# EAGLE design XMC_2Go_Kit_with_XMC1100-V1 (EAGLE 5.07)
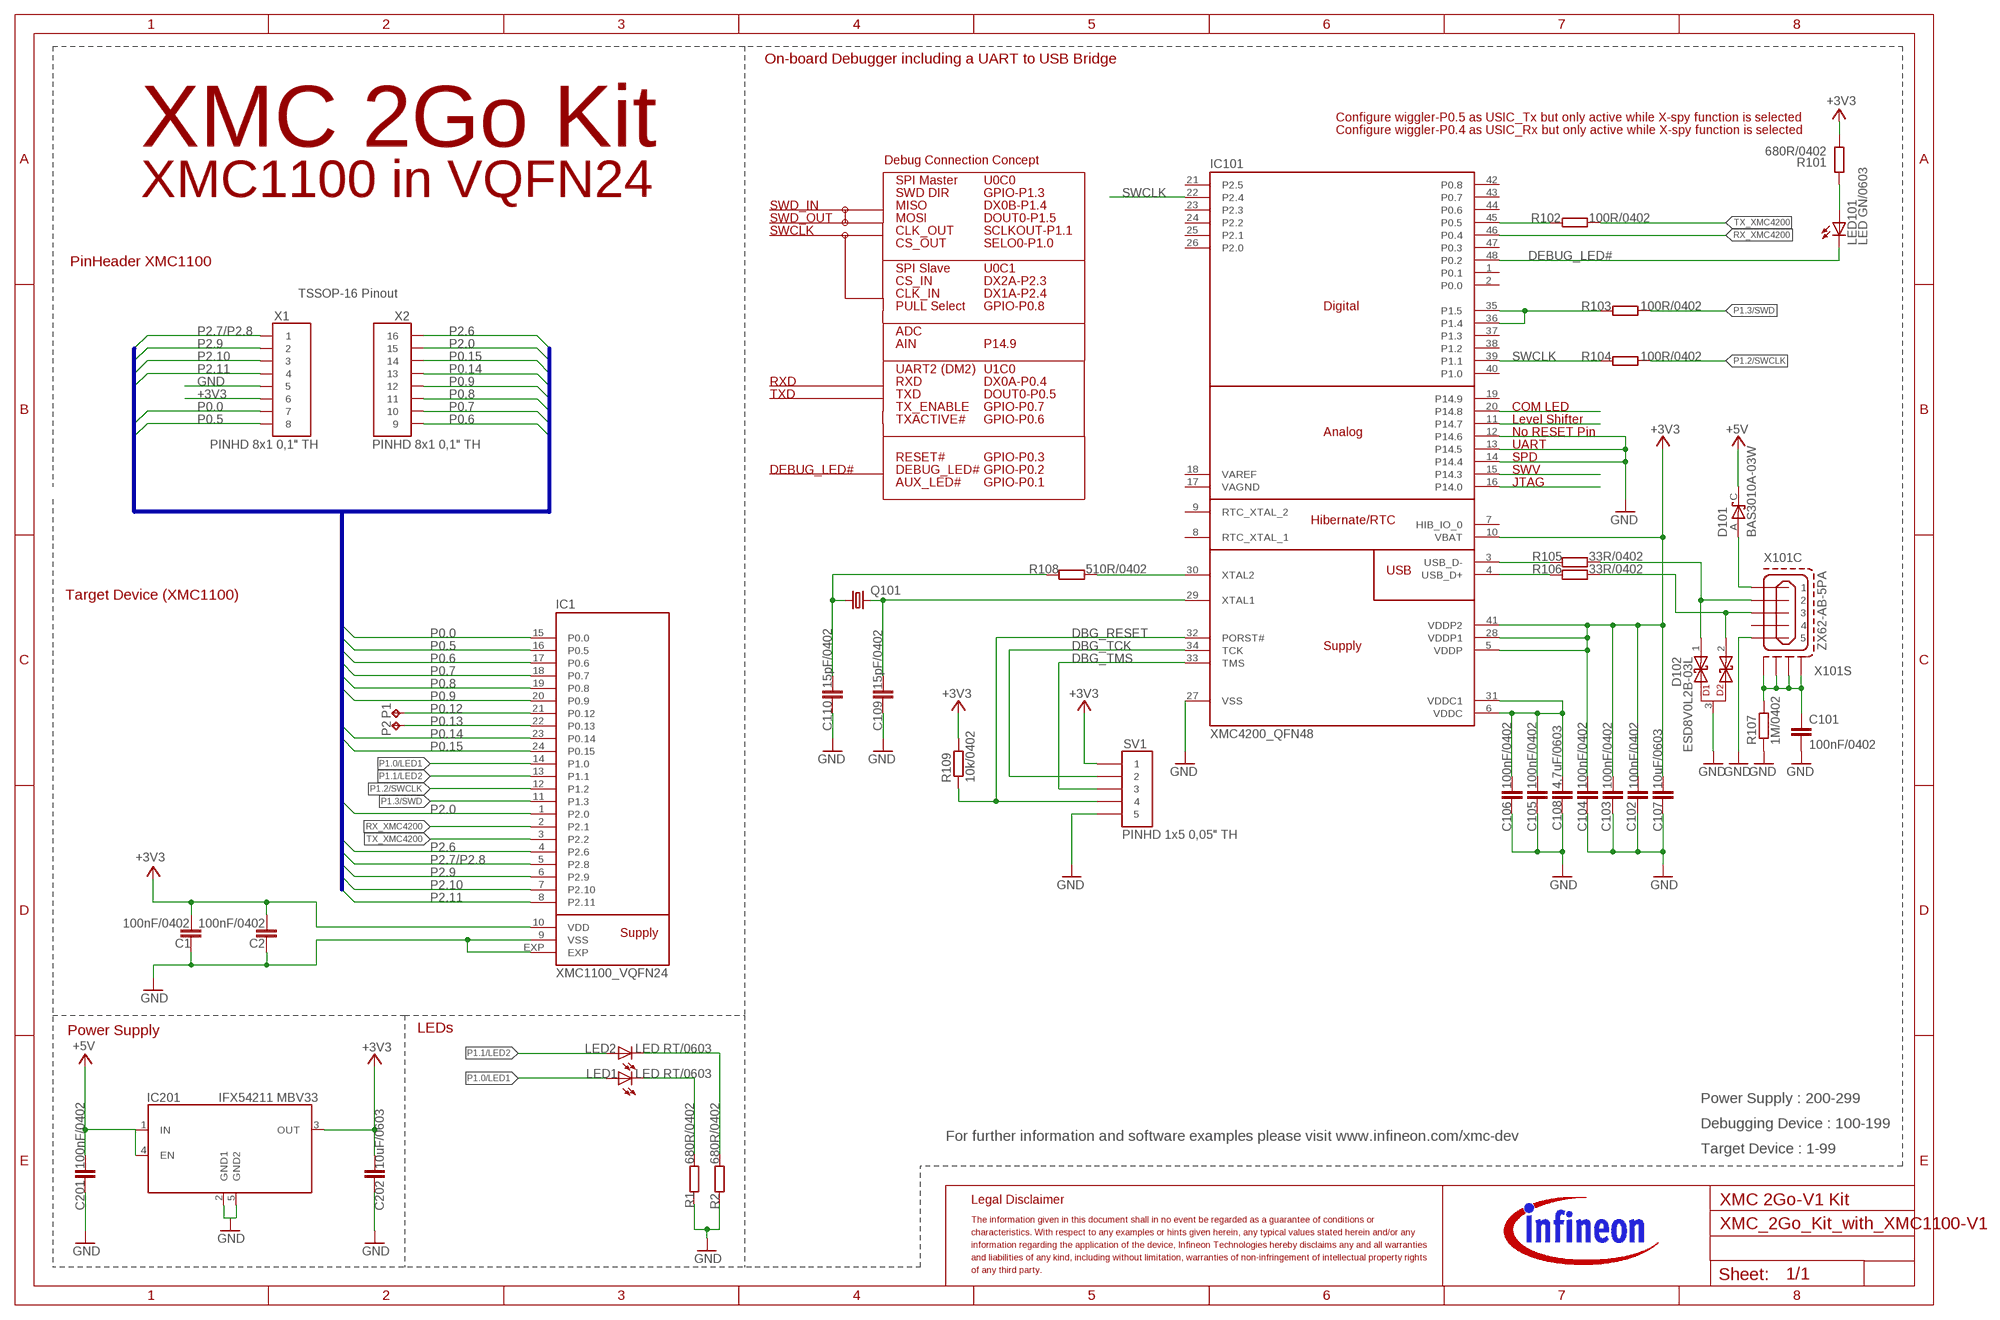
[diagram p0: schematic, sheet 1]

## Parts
C1  100nF/0402  C-EUC0402  [C0402]
C2  100nF/0402  C-EUC0402  [C0402]
C101  100nF/0402  C-EUC0402  [C0402]
C102  100nF/0402  C-EUC0402  [C0402]
C103  100nF/0402  C-EUC0402  [C0402]
C104  100nF/0402  C-EUC0402  [C0402]
C105  100nF/0402  C-EUC0402  [C0402]
C106  100nF/0402  C-EUC0402  [C0402]
C107  10uF/0603  C-EUC0603  [C0603]
C108  4,7uF/0603  C-EUC0603  [C0603]
C109  15pF/0402  C-EUC0402  [C0402]
C110  15pF/0402  C-EUC0402  [C0402]
C201  100nF/0402  C-EUC0402  [C0402]
C202  10uF/0603  C-EUC0603  [C0603]
D101  BAS3010A-03W  BAT60  [SOD323-R]
D102  ESD8V0L2B-03L  [TSLP-3-1]
IC1  XMC1100_VQFN24  [VQFN24]
IC101  XMC4200_QFN48  [QFN-48-7X7]
IC201  IFX54211 MBV33  TLS202B1MBV  [SCT595_INFINEON]
LED1  LED RT/0603  LEDCHIPLED_0603  [CHIPLED_0603]
LED2  LED RT/0603  LEDCHIPLED_0603  [CHIPLED_0603]
LED101  LED GN/0603  LEDCHIPLED_0603  [CHIPLED_0603]
P1  TPTP07R  [TP07R]
P2  TPTP07R  [TP07R]
Q101  NX3225_2  [32X25_4PAD]
R1  680R/0402  R-EU_R0402  [R0402]
R2  680R/0402  R-EU_R0402  [R0402]
R101  680R/0402  R-EU_R0402  [R0402]
R102  100R/0402  R-EU_R0402  [R0402]
R103  100R/0402  R-EU_R0402  [R0402]
R104  100R/0402  R-EU_R0402  [R0402]
R105  33R/0402  R-EU_R0402  [R0402]
R106  33R/0402  R-EU_R0402  [R0402]
R107  1M/0402  R-EU_R06030402  [R0402]
R108  510R/0402  R-EU_R0402  [R0402]
R109  10k/0402  R-EU_R0402  [R0402]
SV1  PINHD 1x5 0,05" TH  PINHEAD_127  [PINHEAD_127]
X1  PINHD 8x1 0,1" TH  PINHD_1X8_SP  [PINHD_1X8_SP]
X2  PINHD 8x1 0,1" TH  PINHD_1X8_SP  [PINHD_1X8_SP]
X101  ZX62-AB-5PA  ZX62-AB-5PA_MICRO-USB  [ZX62-AB-5PA_MICRO-USB]

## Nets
+3V3: C1.2 C2.2 C102.1 C103.1 C104.1 C107.1 C202.1 IC1.10(VDD) IC101.5(VDDP) IC101.10(VBAT) IC101.28(VDDP1) IC101.41(VDDP2) IC201.3(OUT) R101.1 R109.2 SV1.P$1 X1.6
+5V: C201.1 D101.C IC201.1(IN) IC201.4(EN)
DBG_RESET: IC101.32(PORST#) R109.1 SV1.P$4
DBG_TCK: IC101.34(TCK) SV1.P$2
DBG_TMS: IC101.33(TMS) SV1.P$3
DEBUG_LED#: IC101.48(P0.2) LED101.C
GND: C1.1 C2.1 C101.2 C102.2 C103.2 C104.2 C105.2 C106.2 C107.2 C108.2 C109.2 C110.2 C201.2 C202.2 D102.3 IC1.9(VSS) IC1.EXP IC101.12(P14.6) IC101.13(P14.5) IC101.14(P14.4) IC101.27(VSS) IC201.2(GND1) IC201.5(GND2) R1.1 R2.1 R107.1 SV1.P$5 X1.5 X101.5
N$1: LED1.C R1.2
N$2: IC101.35(P1.5) IC101.36(P1.4) R103.1
N$3: LED2.C R2.2
N$6: IC101.45(P0.5) R102.1
N$7: IC101.20(P14.8)
N$8: IC101.11(P14.7)
N$20: IC101.16(P14.0)
N$21: IC101.15(P14.3)
N$23: C101.1 R107.2 X101.S1(S:S1) X101.S2(S:S2) X101.S3(S:S3) X101.S4(S:S4)
N$36: LED101.A R101.2
N$40: D102.1 R105.2 X101.2
N$41: D102.2 R106.2 X101.3
N$42: IC101.30(XTAL2) R108.2
N$43: C110.1 Q101.1 R108.1
P0.0: IC1.15(P0.0) X1.7
P0.5: IC1.16(P0.5) X1.8
P0.6: IC1.17(P0.6) X2.8
P0.7: IC1.18(P0.7) X2.7
P0.8: IC1.19(P0.8) X2.6
P0.9: IC1.20(P0.9) X2.5
P0.12: IC1.21(P0.12) P1.TP
P0.13: IC1.22(P0.13) P2.TP
P0.14: IC1.23(P0.14) X2.4
P0.15: IC1.24(P0.15) X2.3
P1.0/LED1: IC1.14(P1.0) LED1.A
P1.1/LED2: IC1.13(P1.1) LED2.A
P1.2/SWCLK: IC1.12(P1.2) R104.2
P1.3/SWD: IC1.11(P1.3) R103.2
P2.0: IC1.1(P2.0) X2.2
P2.6: IC1.4(P2.6) X2.1
P2.7/P2.8: IC1.5(P2.8) X1.P$1
P2.9: IC1.6(P2.9) X1.2
P2.10: IC1.7(P2.10) X1.3
P2.11: IC1.8(P2.11) X1.4
Q200: C109.1 IC101.29(XTAL1) Q101.3
RX_XMC4200: IC1.2(P2.1) IC101.46(P0.4)
SWCLK: IC101.22(P2.4) IC101.39(P1.1) R104.1
TX_XMC4200: IC1.3(P2.2) R102.2
USBVCC: D101.A X101.1
WUSB_DM: IC101.3(USB_D-) R105.1
WUSB_DP: IC101.4(USB_D+) R106.1
WVDDC: C105.1 C106.1 C108.1 IC101.6(VDDC) IC101.31(VDDC1)
Unconnected: IC101.1(P0.1) IC101.2(P0.0) IC101.7(HIB_IO_0) IC101.8(RTC_XTAL_1) IC101.9(RTC_XTAL_2) IC101.17(VAGND) IC101.18(VAREF) IC101.19(P14.9) IC101.21(P2.5) IC101.23(P2.3) IC101.24(P2.2) IC101.25(P2.1) IC101.26(P2.0) IC101.37(P1.3) IC101.38(P1.2) IC101.40(P1.0) IC101.42(P0.8) IC101.43(P0.7) IC101.44(P0.6) IC101.47(P0.3) X101.4

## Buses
P2.6,P2.0,P0.15/SWCLK,P0.14/SWD,P0.9,P0.8,P0.7,P0.6,P0.5,P0.0,P2.11,P2.10,P2.9,P2.7/P2.8

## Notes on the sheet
- On-board Debugger including a UART to USB Bridge
- Configure wiggler-P0.5 as USIC_Tx but only active while X-spy function is selected
- Configure wiggler-P0.4 as USIC_Rx but only active while X-spy function is selected
- XMC 2Go Kit
- Debug Connection Concept
- SPI Master | U0C0
- XMC1100 in VQFN24 | SWD DIR | GPIO-P1.3
- SWD_IN | MISO | DX0B-P1.4
- SWD_OUT | MOSI | DOUT0-P1.5
- SWCLK | CLK_OUT | SCLKOUT-P1.1
- CS_OUT | SELO0-P1.0
- PinHeader XMC1100
- SPI Slave | U0C1
- CS_IN | DX2A-P2.3
- TSSOP-16 Pinout | CLK_IN | DX1A-P2.4
- PULL Select | GPIO-P0.8
- ADC
- 1 | 16
- AIN | P14.9
- 2 | 15
- 3 | 14
- UART2 (DM2) | U1C0
- 4 | 13
- RXD | RXD | DX0A-P0.4
- 5 | 12
- TXD | TXD | DOUT0-P0.5
- 6 | 11
- TX_ENABLE | GPIO-P0.7 | COM LED
- 7 | 10
- TXACTIVE# | GPIO-P0.6 | Level Shifter
- 8 | 9
- No RESET Pin
- UART
- RESET# | GPIO-P0.3 | SPD
- DEBUG_LED# | DEBUG_LED# | GPIO-P0.2 | SWV
- AUX_LED# | GPIO-P0.1 | JTAG
- Target Device (XMC1100)
- Power Supply | LEDs
- Power Supply : 200-299
- Debugging Device : 100-199
- For further information and software examples please visit www.infineon.com/xmc-dev
- Target Device : 1-99
- XMC 2Go-V1 Kit

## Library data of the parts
C1 C2 C101-C106 C109 C110 C201 = DsC:C-EUC0402
C107 C108 C202 = rcl:C-EU: CAPACITOR, European symbol
D101 = DsDiod:BAT60
D102 = DsDiod:ESD8V0L2B-03L
IC1 = XMC1100:XMC1100_VQFN24
IC101 = XMC4000_v4.16:XMC4200_QFN48
IC201 = TLS202B1:TLS202B1MBV
LED1 LED2 LED101 = led:LED: LED
P1 P2 = testpad:TP: Test pad
Q101 = Quarz:NX3225_2
R1 R2 R101-R106 R108 R109 = DsR:R-EU_R0402
R107 = DsR:R-EU_R0603
SV1 = pinhead_127_marked:PINHEAD_127
X1 = Pinhead_1x8_sp_V2:PINHD_1X8_SP
X2 = Pinhead_1x8_sp:PINHD_1X8_SP
X101 = XSRRND:ZX62-AB-5PA_MICRO-USB

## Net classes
0 default: width 0.178 mm, drill 0.127 mm, clearance 0.2 mm
1 power: width 0.61 mm, drill 0.127 mm, clearance 0.152 mm
2 gnd: width 0.305 mm, drill 0.127 mm, clearance 0.152 mm
3 usbvcc: width 0.508 mm, drill 0.127 mm, clearance 0.152 mm
4 aref: width 0.406 mm

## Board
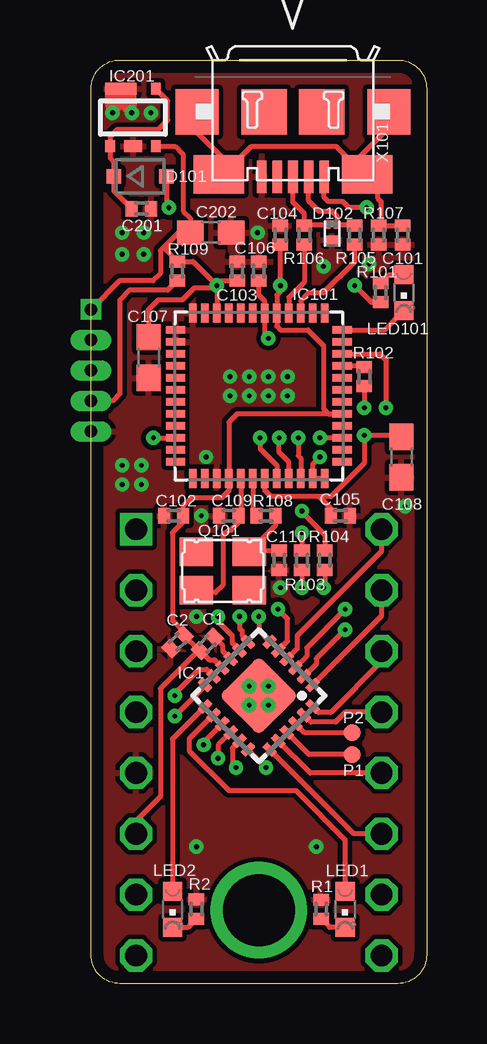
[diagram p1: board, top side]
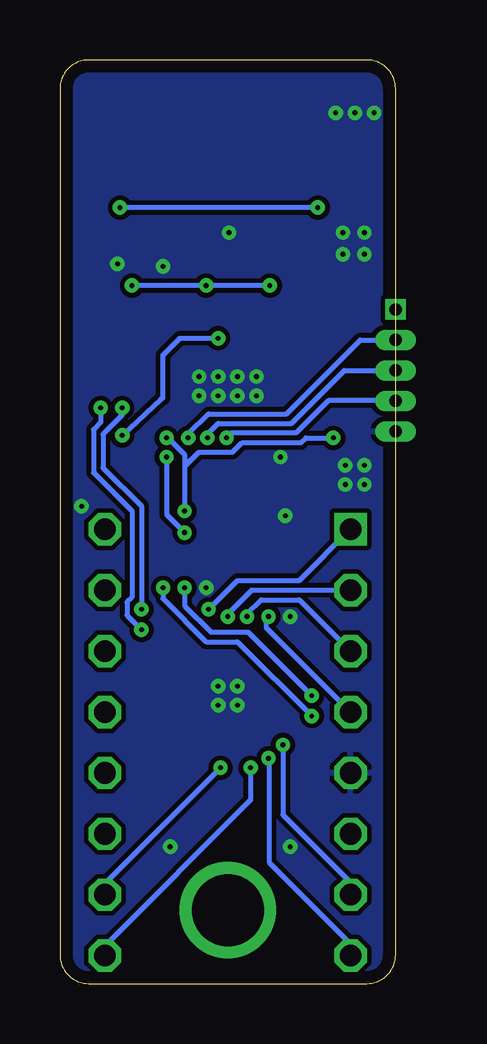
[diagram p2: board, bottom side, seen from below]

Size 14 x 38.5 mm. Coordinates in mm from the lower left corner, seen from the top.
Outline: 0,37.3 arc-90 1.2,38.5 12.8,38.5 arc-90 14,37.3 14,1.2 arc-90 12.8,0 1.2,0 arc-90 0,1.2 0,37.3
Copper layers (1*16): Top 0.035mm / dielectric 1.5mm / Bottom 0.035mm
Design rules "Relax_V2 *": minimum track width 0.2mm, minimum drill 0.2mm, track to track 0.2mm, track to pad 0.2mm, pad to pad 0.2mm, via to via 0.2mm, smd to smd 0.2mm, copper to edge 0.5mm, drill to drill 0.5mm, minimum pad ring 7mil, minimum via ring 0.2mm, stop-mask expansion 4mil, vias tented up to drill 0.25mm, thermal gap 0.2mm
tRestrict: 4 lines

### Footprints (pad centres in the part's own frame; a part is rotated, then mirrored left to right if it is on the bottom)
C0402 = smd 0.5 x 0.65: 1 -0.4,0; 2 0.4,0
C0603 = smd 1.1 x 1: 1 -0.85,0; 2 0.85,0
SOD323-R = smd 0.6 x 0.6: A 1.1,0; C -1.1,0
TSLP-3-1 = smd 0.225 x 0.35: 1 0.113,-0.475; 2 0.487,-0.475 | smd 0.6 x 0.35: 3 0.3,0.175
VQFN24 = smd 0.6 x 0.3: 1 -1.905,1.27; 2 -1.905,0.762; 3 -1.905,0.254; 4 -1.905,-0.254; 5 -1.905,-0.762; 6 -1.905,-1.27; 13 1.905,-1.27; 14 1.905,-0.762; 15 1.905,-0.254; 16 1.905,0.254; 17 1.905,0.762; 18 1.905,1.27 | smd 0.3 x 0.6: 7 -1.27,-1.905; 8 -0.762,-1.905; 9 -0.254,-1.905; 10 0.254,-1.905; 11 0.762,-1.905; 12 1.27,-1.905; 19 1.27,1.905; 20 0.762,1.905; 21 0.254,1.905; 22 -0.254,1.905; 23 -0.762,1.905; 24 -1.27,1.905 | smd 2.35 x 2.35: EXP 0,0
QFN-48-7X7 = smd 0.8 x 0.3: 1 -3.45,2.75; 2 -3.45,2.25; 3 -3.45,1.75; 4 -3.45,1.25; 5 -3.45,0.75; 6 -3.45,0.25; 7 -3.45,-0.25; 8 -3.45,-0.75; 9 -3.45,-1.25; 10 -3.45,-1.75; 11 -3.45,-2.25; 12 -3.45,-2.75; 25 3.45,-2.75; 26 3.45,-2.25; 27 3.45,-1.75; 28 3.45,-1.25; 29 3.45,-0.75; 30 3.45,-0.25; 31 3.45,0.25; 32 3.45,0.75; 33 3.45,1.25; 34 3.45,1.75; 35 3.45,2.25; 36 3.45,2.75 | smd 0.3 x 0.8: 13 -2.75,-3.475; 14 -2.25,-3.475; 15 -1.75,-3.475; 16 -1.25,-3.475; 17 -0.75,-3.475; 18 -0.25,-3.475; 19 0.25,-3.475; 20 0.75,-3.475; 21 1.25,-3.475; 22 1.75,-3.475; 23 2.25,-3.475; 24 2.75,-3.475; 37 2.75,3.475; 38 2.25,3.475; 39 1.75,3.475; 40 1.25,3.475; 41 0.75,3.475; 42 0.25,3.475; 43 -0.25,3.475; 44 -0.75,3.475; 45 -1.25,3.475; 46 -1.75,3.475; 47 -2.25,3.475; 48 -2.75,3.475
SCT595_INFINEON = smd 0.4 x 0.5: 1 -0.95,-1.2; 3 0.95,-1.2; 4 0.95,1.2 | smd 0.75 x 0.5: 2 0,-1.2 | smd 1.3 x 0.5: 5 -0.5,1.2
CHIPLED_0603 = smd 0.8 x 0.8: A 0,-0.75; C 0,0.75
TP07R = smd 0.7 x 0.7: TP 0,0
32X25_4PAD = smd 1.4 x 1.2: 1 -1.1,-0.8; 2 1.1,-0.8; 3 1.1,0.8; 4 -1.1,0.8
R0402 = smd 0.5 x 0.65: 1 -0.4,0; 2 0.4,0
PINHEAD_127 = drill 0.508 square: P$1 0,0 | drill 0.508 long: P$2 0,-1.27; P$3 0,-2.54; P$4 0,-3.81; P$5 0,-5.08
PINHD_1X8_SP = drill 0.9 octagon: 2 0,7.62; 3 0,5.08; 4 0,2.54; 5 0,0; 6 0,-2.54; 7 0,-5.08; 8 0,-7.62 | drill 0.9 square: P$1 0,10.16
PINHD_1X8_SP' = drill 0.9 octagon: 1 0,10.16; 2 0,7.62; 3 0,5.08; 4 0,2.54; 5 0,0; 6 0,-2.54; 7 0,-5.08; 8 0,-7.62
ZX62-AB-5PA_MICRO-USB = smd 0.4 x 1.35: 1 -1.3,1.45; 2 -0.65,1.45; 3 0,1.45; 4 0.65,1.45; 5 1.3,1.45 | smd 2.1 x 1.6: S1 -3.1,1.35; S2 3.1,1.35 | smd 1.8 x 1.9: S3 -4,-1.25; S4 4,-1.25 | smd 1.9 x 1.9: S5 -1.2,-1.25; S6 1.2,-1.25

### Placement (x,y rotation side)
C1  4.85,14.15 225 top
C2  3.61,14.23 45 top
C101  13,31.2 270 top
C102  3.45,19.5 180 top
C103  6.1,29.7 90 top
C104  7.9,31.2 90 top
C105  10.4,19.5 0 top
C106  7,29.7 90 top
C107  2.4,26.1 270 top
C108  12.95,21.95 270 top
C109  5.75,19.5 180 top
C110  7.85,17.65 270 top
C201  2.1,32.3 0 top
C202  5,31.3 0 top
D101  2.05,33.65 0 top
D102  10.36,31.17 180 top
IC1  7,12 225 top
IC101  7,24.5 270 top
IC201  1.75,36.1 0 top
LED1  10.6,3.09 180 top
LED2  3.4,3.1 180 top
LED101  13.05,28.8 180 top
P1  10.9,9.55 0 top
P2  10.9,10.45 0 top
Q101  5.5,17.2 180 top
R1  9.6,3.1 270 top
R2  4.4,3.1 270 top
R101  12.08,28.8 90 top
R102  11.4,25.3 270 top
R103  8.8,17.65 270 top
R104  9.75,17.65 270 top
R105  11,31.2 90 top
R106  8.9,31.2 90 top
R107  12,31.2 90 top
R108  7.3,19.5 180 top
R109  3.6,29.7 90 top
SV1  0,28.1 0 top
U$2  [INFINEON_LOGO_INFINEON_LOGO_5_SILK]  6.3,34.6 270 bottom
U$3  [CE_KENNEZCIHNUNG]  6.91,8.72 180 bottom
X1  1.88,8.78 0 top
X2  PINHD 8x1 0,1" TH  [PINHD_1X8_SP']  12.12,8.78 0 top
X101  8.42,35.08 180 top

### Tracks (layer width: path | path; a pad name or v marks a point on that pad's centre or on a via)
+3V3  (via drill 0.2)
  Top 0.2: IC201.3 3.5,34.9 3.85,34.55 3.85,32.2 4.15,31.9 C202.1 | SV1.P$1 1.2,29.3 2.6,29.3 2.9,29.6 2.9,30.55 3.12,30.77 | 3.12,30.77 3.65,31.3 C202.1 | 3.12,30.77 3.12,30.57 R109.2 4.25,30.1 v5.25,29.1 | C104.1 v7.9,29.1 7.9,28.85 7.75,28.7 IC101.5 7.75,27.4 7.9,27.25 9.05,27.25 9.7,26.6 9.7,23.95 9.9,23.75 IC101.41 6.1,23.75 5.75,23.4 IC101.28 5.75,20.55 5.45,20.25 4.2,20.25 3.85,19.9 C102.1 | v5.25,29.1 IC101.10 | C202.1 4.3,31.3 | C103.1 5.45,29.3 v5.25,29.1 | C1.2 4.62,13.82 | 4.47,13.87 C1.2 | IC1.10 5.15,13.5 4.93,13.5 C1.2 | C107.1 2.4,28.1 2.8,28.5 3.8,28.5 4.3,29 5.15,29 v5.25,29.1 | 4.47,13.87 4.47,13.94 C2.2 3.89,14.64 3.4,15.13 3.4,18.8 3.85,19.25 C102.1 | X1.6 1.88,6.78 2.9,7.8 2.9,12.3 4.47,13.87 | C102.1 3.8,19.3 | R101.1 11.7,28.4 v11,29.1
  Bottom 0.2: v5.25,29.1 v7.9,29.1 v11,29.1
+5V
  Top 0.2: C201.1 0.95,33.05 D101.C 0.95,34.25 0.8,34.4 IC201.1 0.8,35.3 1.1,35.6 2.8,35.6 3.2,36 3.2,36.8 IC201.4
DBG_RESET  (via drill 0.2)
  Top 0.2: R109.1 3.2,28.9 1.6,28.9 1.2,28.5 1.2,24.59 0.9,24.29 SV1.P$4 0.64,24.29 | IC101.32 7.75,21.6 7.05,22.3 v7.05,22.75
  Bottom 0.2: SV1.P$4 2.8,24.3 4.15,22.95 6.85,22.95 v7.05,22.75
DBG_TCK  (via drill 0.2)
  Top 0.2: IC101.34 8.75,21.9 8.65,22 v8.65,22.75
  Bottom 0.2: SV1.P$2 1.47,26.83 4.55,23.75 7.8,23.75 8.65,22.9 v8.65,22.75
DBG_TMS  (via drill 0.2)
  Top 0.2: IC101.33 8.25,21.75 7.85,22.15 v7.85,22.75
  Bottom 0.2: SV1.P$3 2.14,25.56 4.35,23.35 7.4,23.35 7.85,22.9 v7.85,22.75
DEBUG_LED#
  Top 0.2: LED101.C 12.25,27.25 IC101.48
GND  (via drill 0.2)
  Top 0.2: IC101.27 5.2,21.1 | IC1.9 5.5,13.85 5.5,14.07 C1.1
  Top 0.7: 0.95,36.62 0.95,37.15 | 1.55,36.65 1.55,37.18
  other vias: 9.7,29.9 6.6,24.5 7.4,24.5 6.6,25.3 7.4,25.3 8.2,25.3 8.2,24.5 6.95,31.3 11.6,30 5.8,25.3 5.8,24.5 1.3,31.3 2.2,31.3 2.2,30.4 1.3,30.4 1.3,21.6 2.1,21.6 2.1,20.8 1.3,20.8 4.4,15.3 13.1,19.9 4.6,19.5 0.9,36.3 1.7,36.3 2.5,36.3 4.4,5.7 9.4,5.7 7.4,11.6 6.6,12.4 7.4,12.4 6.6,11.6 4.8,21.95 7.9,16.5
  pour Top (isolate 0.2): 0,0 0,38.5 14,38.5 14,0
  pour Bottom: 0,38.5 14,38.5 14,0 0,0
N$1
  Top 0.2: R1.2 9.96,2.34 LED1.C
N$2  (via drill 0.2)
  Top 0.2: v8.8,18.8 R103.1 | v9.55,21.95 9.25,21.65 IC101.35 IC101.36
  Bottom 0.2: v8.8,18.8 9.55,19.55 v9.55,21.95
N$3
  Top 0.2: R2.2 4.05,2.35 LED2.C
N$5  (via drill 3)
  other vias: 7,3.06
N$6
  Top 0.2: R102.1 11.35,25.75 IC101.45
N$23
  Top 0.2: C101.1 R107.2 12.1,31.7 | 11.87,33.25 X101.S1 | X101.S2 5.22,33.42 6.1,34.3 | 10.82,34.3 11.87,33.25 | 12.1,31.7 12.2,31.7 | 6.1,34.3 5.6,34.3 4.32,35.58 X101.S4 | 10.82,34.3 11.04,34.3 12.32,35.58 X101.S3 | 11.87,33.25 11.95,33.25 11.95,32.75 12.1,32.6 12.1,31.7 | 6.1,34.3 6.7,34.9 10.22,34.9 10.82,34.3
N$36
  Top 0.2: R101.2 12.43,29.55 LED101.A
N$40
  Top 0.2: 10.9,31.7 R105.2 10.95,31.75 10.85,31.64 D102.1 10.25,31.75 10.25,32 10.05,32.2 9.5,32.2 9.07,32.63 X101.2
N$41
  Top 0.2: D102.2 8.95,31.64 R106.2 8.9,32.1 8.42,32.58 X101.3
N$42
  Top 0.2: IC101.30 6.75,19.65 R108.2
N$43
  Top 0.2: 6.82,17.95 Q101.1 6.95,18.35 | R108.1 7.7,19.1 6.95,18.35 | C110.1 7.25,18.05 6.95,18.35
P0.0  (via drill 0.2)
  Top 0.2: v4.7,9.95 4.7,10.06 IC1.15
  Bottom 0.2: v4.7,9.95 4.7,7.04 1.88,4.22 X1.7
P0.5  (via drill 0.2)
  Top 0.2: IC1.16 5.3,9.94 v5.3,9.39
  Bottom 0.2: v5.3,9.39 5.28,9.37 5.28,5.06 1.88,1.66 X1.8
P0.6  (via drill 0.2)
  Top 0.2: IC1.17 5.9,9.82 5.9,9.15 v6.05,9
  Bottom 0.2: X2.8 12.12,1.58 6.05,7.65 v6.05,9
P0.7  (via drill 0.2)
  Top 0.2: IC1.18 v7.3,9
  Bottom 0.2: v7.3,9 12.12,4.18 X2.7
P0.8
  Top 0.2: IC1.19 10.96,6.24 X2.6
P0.9
  Top 0.2: IC1.20 9.14,8.78 X2.5
P0.12
  Top 0.2: IC1.21 9.09,9.55 P1.TP
P0.13
  Top 0.2: IC1.22 8.91,10.45 P2.TP
P0.14
  Top 0.2: IC1.23 9.18,10.9 10.2,10.9 10.62,11.32 X2.4
P0.15
  Top 0.2: IC1.24 9.5,11.3 10,11.3 12.12,13.42 X2.3
P1.0/LED1
  Top 0.2: 10.6,4.01 LED1.A 10.6,6 8.55,8.05 5.75,8.05 4.1,9.7 4.1,10.2 5.09,11.19 IC1.14
P1.1/LED2
  Top 0.2: IC1.13 3.4,10.2 LED2.A
P1.2/SWCLK  (via drill 0.2)
  Top 0.2: v3.5,11.15 4.75,12.41 IC1.12 | R104.2 9.75,16.55 v9.7,16.5
  Bottom 0.2: v3.5,11.15 6.6,14.25 7.9,14.25 9.7,16.05 v9.7,16.5
P1.3/SWD  (via drill 0.2)
  Top 0.2: IC1.11 5.09,12.81 | IC1.11 5.11,12.86 | v3.5,12 3.5,12.1 4.5,13.1 4.82,13.1 IC1.11 | R103.2 v8.8,16.5
  Bottom 0.2: v3.5,12 6.15,14.65 7.7,14.65 8.8,15.75 v8.8,16.5
P2.0
  Top 0.2: IC1.1 12.12,15.32 X2.2
P2.6
  Top 0.2: 8.17,13.57 IC1.4 8.6,13.96 8.6,14.5 12.12,18.02 X2.1
P2.7/P2.8  (via drill 0.2)
  Top 0.2: IC1.5 8.2,14.28 8.2,15.2 v7.8,15.6
  Bottom 0.2: X1.P$1 4.02,16.8 6.6,16.8 v7.8,15.6
P2.9  (via drill 0.2)
  Top 0.2: IC1.6 7,14.69 v7,15.3
  Bottom 0.2: X1.2 6,16.4 7,15.4 v7,15.3
P2.10  (via drill 0.2)
  Top 0.2: IC1.7 6.3,14.5 6.3,14.7 6.2,14.8 v6.2,15.3
  Bottom 0.2: v6.2,15.3 6.2,15.4 5.6,16 4.02,16 X1.3
P2.11  (via drill 0.2)
  Top 0.2: IC1.8 6.19,13.91 5.9,14.2 5.9,14.5 5.4,15 5.4,15.2 v5.3,15.3
  Bottom 0.2: X1.4 5.4,14.84 5.4,15.2 v5.3,15.3
Q200
  Top 0.2: IC101.29 6.25,19.6 C109.1 6.15,19.2 5.85,18.9 5.75,18.9 5.65,18.8 5.6,18.8 5.5,18.7 5.5,16.6 5.2,16.3 4.45,16.3 Q101.3
RX_XMC4200  (via drill 0.2)
  Top 0.2: v12.3,24 12.3,26 12.05,26.25 IC101.46 | IC1.2 9.4,13.32 9.4,13.55 v10.6,14.75
  Bottom 0.2: v12.3,24 12.3,23.4 12.6,23.1 12.6,21.3 11,19.7 11,16.1 11.2,15.9 11.2,15.35 v10.6,14.75
SWCLK  (via drill 0.2)
  Top 0.2: IC101.39 v9.55,22.75 | v2.6,22.75 IC101.22 | R104.1 9.75,18.7 8.8,19.65 v8.8,19.7
  Bottom 0.2: 8.55,21.8 8.2,22.15 6.8,22.15 6.4,22.55 3.95,22.55 3.75,22.75 v2.6,22.75 | 8.55,21.8 8.6,21.8 | 8.8,21.55 v8.8,19.7 | 8.8,21.55 8.55,21.8 | 8.8,21.55 8.8,22.05 9.5,22.75 v9.55,22.75
TX_XMC4200  (via drill 0.2)
  Top 0.2: R102.2 v11.4,24 | IC1.3 9,13.64 9,14 v10.6,15.6
  Bottom 0.2: v11.4,24 11.4,23.7 12.2,22.9 12.2,21.5 10.6,19.9 v10.6,15.6
USBVCC  (via drill 0.2)
  Top 0.2: v11.5,32.35 10.75,32.35 10.5,32.6 9.9,32.6 9.72,32.78 X101.1 | v3.25,32.35 3.15,32.45 D101.A
  Bottom 0.2: v3.25,32.35 v11.5,32.35
WUSB_DM
  Top 0.2: R105.1 11,30.1 9.7,28.8 9.1,28.8 8.75,28.45 IC101.3
WUSB_DP
  Top 0.2: IC101.4 8.25,28.6 8.9,29.25 R106.1
WVDDC  (via drill 0.2)
  Top 0.2: 9.5,20.3 7.5,20.3 7.25,20.55 IC101.31 | v7.4,26.9 7.25,27.05 IC101.6 7.25,28.45 7,28.7 C106.1 | 12.55,22.7 C108.1 12.75,22.85 v11.4,22.85 11.4,21.7 10,20.3 9.5,20.3 | C105.1 10,19.8 9.5,20.3
  Bottom 0.2: v7.4,26.9 9,26.9 9.7,26.2 9.7,24.4 arc-45 9.79,24.37 v11.4,22.85

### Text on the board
Measures: 38.5 | 14
Reference: 38.5 mm | 14.0 mm
tSilk: XMC1100 | XMC 2Go
bSilk: www.infineon.com/xmc-dev | XMC 2Go-V1 | P2.7 | P2.6 | P2.9 | P2.0 | P2.10 | P0.15 | P2.11 | P0.14 | VSS | P0.9 | VDD | P0.8 | P0.0 | P0.7 | P0.5 | P0.6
